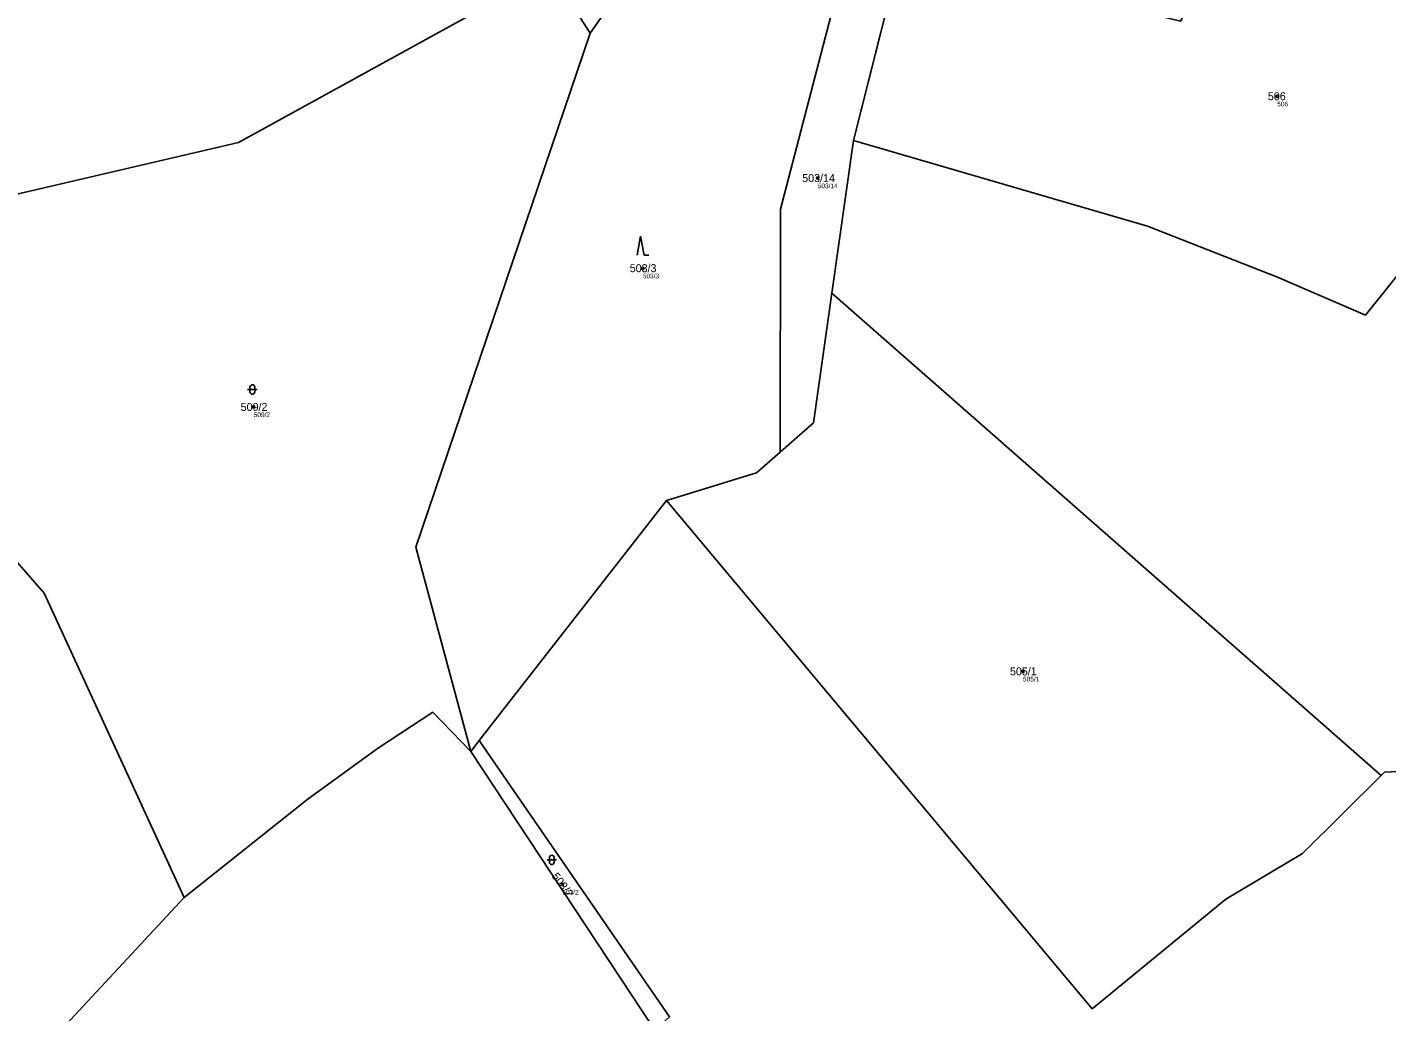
# Model space of a CAD drawing. Extents: x -766177 to -763254, y -1057727 to -1053915.
# Drawn here: x -765482.3 to -765193.5, y -1056306.7 to -1056097.6 of the extents above; entities that cross this region are included whole.
import ezdxf

# ---------------------------------------------------------------- set-up
doc = ezdxf.new("R2010")
doc.units = 0
for name, color, linetype in [('Vrstva 1', 7, 'Continuous'), ('Vrstva 2', 7, 'Continuous'), ('Vrstva 3', 7, 'Continuous'), ('Vrstva 50', 7, 'Continuous'), ('Vrstva 51', 7, 'Continuous')]:
    doc.layers.add(name, color=color, linetype=linetype)

msp = doc.modelspace()

# ---------------------------------------------------------------- linework, layer by layer
at = {"layer": 'Vrstva 1'}
for p, q in [((-765354.54, -1056087.11), (-765362.7, -1056098.87)), ((-765306.77, -1056121.63), (-765298.99, -1056090.69)), ((-765311.38, -1056154.08), (-765306.77, -1056121.63)), ((-765194.66, -1056256.52), (-765311.38, -1056154.08)), ((-765346.48, -1056198.15), (-765386.27, -1056249.12)), ((-765386.27, -1056249.12), (-765388.1, -1056251.45)), ((-765386.27, -1056249.12), (-765345.84, -1056307.83)), ((-765388.1, -1056251.45), (-765349, -1056310.65)), ((-765474.11, -1056309.49), (-765448.97, -1056282.49))]:
    msp.add_line(p, q, dxfattribs=at)
for points in [[(-765362.7, -1056098.87), (-765371.24, -1056085.63), (-765437.45, -1056122.1), (-765507.01, -1056138.29), (-765499.73, -1056153.48), (-765498.19, -1056169.01), (-765497.32, -1056190.86), (-765490.87, -1056203.92), (-765478.74, -1056217.81), (-765448.97, -1056282.49)], [(-765322.36, -1056187.86), (-765322.29, -1056136.23), (-765310.24, -1056089.97)], [(-765362.7, -1056098.87), (-765399.76, -1056208.05), (-765388.1, -1056251.45)], [(-765306.77, -1056121.63), (-765244.31, -1056139.87), (-765216.67, -1056150.71), (-765198.03, -1056158.78), (-765181.05, -1056137.66), (-765166.4, -1056113.67)], [(-765322.36, -1056187.86), (-765315.29, -1056181.63), (-765311.38, -1056154.08)], [(-765346.48, -1056198.15), (-765327.35, -1056192.26), (-765322.36, -1056187.86)], [(-765194.66, -1056256.52), (-765211.4, -1056273.13), (-765227.71, -1056282.83), (-765256.08, -1056306.1), (-765346.48, -1056198.15)], [(-765448.97, -1056282.49), (-765422.65, -1056261.47), (-765407.66, -1056250.64), (-765396.12, -1056243.1), (-765388.1, -1056251.45)], [(-765129.94, -1056253.12), (-765143.58, -1056253.3), (-765193.95, -1056255.81), (-765194.66, -1056256.52)]]:
    msp.add_lwpolyline(points, dxfattribs=at)
at = {"layer": 'Vrstva 3'}
for p, q in [((-765352, -1056141.98), (-765352.75, -1056145.98)), ((-765351.25, -1056145.98), (-765352, -1056141.98)), ((-765351.25, -1056145.98), (-765350.254, -1056145.98)), ((-765435.481, -1056174.541), (-765433.479, -1056174.541)), ((-765434.981, -1056174.041), (-765434.981, -1056175.042)), ((-765433.979, -1056175.042), (-765433.979, -1056174.041)), ((-765371.881, -1056274.481), (-765369.879, -1056274.481)), ((-765371.381, -1056273.981), (-765371.381, -1056274.982)), ((-765370.379, -1056274.982), (-765370.379, -1056273.981))]:
    msp.add_line(p, q, dxfattribs=at)
for centre, start, end in [((-765434.48, -1056174.0409), 0, 180), ((-765434.48, -1056175.0409), 180, 359.9878861), ((-765370.88, -1056273.9809), 0, 180), ((-765370.88, -1056274.9809), 180, 359.9878861)]:
    msp.add_arc(centre, 0.5, start, end, dxfattribs=at)
at = {"layer": 'Vrstva 50'}
for centre in [(-765216.77, -1056112.23994), (-765314.37, -1056129.62994), (-765351.54, -1056148.76994), (-765434.19, -1056178.24994), (-765270.76, -1056234.40994), (-765368.62, -1056279.68994)]:
    msp.add_circle(centre, 0.25, dxfattribs=at)
at = {"layer": 'Vrstva 51'}
for points in [[(-765507.01, -1056138.29), (-765437.45, -1056122.1), (-765371.24, -1056085.63), (-765362.7, -1056098.87), (-765354.54, -1056087.11), (-765353.46, -1056085.55), (-765369.17, -1056044.32), (-765393.26, -1056031.51), (-765387.38, -1056062.54), (-765593.55, -1056076.37)], [(-765143.58, -1056253.3), (-765193.95, -1056255.81), (-765194.66, -1056256.52), (-765211.4, -1056273.13), (-765227.71, -1056282.83), (-765256.08, -1056306.1), (-765346.48, -1056198.15), (-765386.27, -1056249.12), (-765345.84, -1056307.83)], [(-765474.11, -1056309.49), (-765448.97, -1056282.49), (-765478.74, -1056217.81), (-765490.87, -1056203.92)]]:
    msp.add_lwpolyline(points, dxfattribs=at)
for points in [[(-765223.4, -1056070.73), (-765237.3, -1056096.28), (-765296.76, -1056081.82), (-765298.99, -1056090.69), (-765306.77, -1056121.63), (-765244.31, -1056139.87), (-765216.67, -1056150.71), (-765198.03, -1056158.78), (-765181.05, -1056137.66), (-765166.4, -1056113.67), (-765143.12, -1056077.62), (-765218.53, -1056055.16)], [(-765499.73, -1056153.48), (-765498.19, -1056169.01), (-765497.32, -1056190.86), (-765490.87, -1056203.92), (-765478.74, -1056217.81), (-765448.97, -1056282.49), (-765422.65, -1056261.47), (-765407.66, -1056250.64), (-765396.12, -1056243.1), (-765388.1, -1056251.45), (-765399.76, -1056208.05), (-765362.7, -1056098.87), (-765371.24, -1056085.63), (-765437.45, -1056122.1), (-765507.01, -1056138.29)], [(-765327.35, -1056192.26), (-765322.36, -1056187.86), (-765322.29, -1056136.23), (-765310.24, -1056089.97), (-765346.41, -1056087.63), (-765354.54, -1056087.11), (-765362.7, -1056098.87), (-765399.76, -1056208.05), (-765388.1, -1056251.45), (-765386.27, -1056249.12), (-765346.48, -1056198.15)], [(-765311.38, -1056154.08), (-765306.77, -1056121.63), (-765298.99, -1056090.69), (-765306.29, -1056090.22), (-765310.24, -1056089.97), (-765322.29, -1056136.23), (-765322.36, -1056187.86), (-765315.29, -1056181.63)], [(-765092.46, -1056129.68), (-765166.4, -1056113.67), (-765181.05, -1056137.66), (-765198.03, -1056158.78), (-765216.67, -1056150.71), (-765244.31, -1056139.87), (-765306.77, -1056121.63), (-765311.38, -1056154.08), (-765194.66, -1056256.52), (-765193.95, -1056255.81), (-765143.58, -1056253.3), (-765129.94, -1056253.12), (-765101.53, -1056228.97), (-765091.79, -1056194.41), (-765081.16, -1056173.51), (-765076.46, -1056159.28), (-765086.71, -1056136.98)], [(-765194.66, -1056256.52), (-765311.38, -1056154.08), (-765315.29, -1056181.63), (-765322.36, -1056187.86), (-765327.35, -1056192.26), (-765346.48, -1056198.15), (-765256.08, -1056306.1), (-765227.71, -1056282.83), (-765211.4, -1056273.13)], [(-765435.92, -1056414.68), (-765423, -1056395.3), (-765411.65, -1056380.15), (-765373.52, -1056336.95), (-765349, -1056310.65), (-765388.1, -1056251.45), (-765396.12, -1056243.1), (-765407.66, -1056250.64), (-765422.65, -1056261.47), (-765448.97, -1056282.49), (-765474.11, -1056309.49), (-765468.33, -1056330.83), (-765477.15, -1056357.39), (-765460.21, -1056386.5), (-765438.68, -1056395.45), (-765445.32, -1056404.44)], [(-765388.1, -1056251.45), (-765349, -1056310.65), (-765345.84, -1056307.83), (-765386.27, -1056249.12)]]:
    msp.add_lwpolyline(points, close=True, dxfattribs=at)

# ---------------------------------------------------------------- texts
at = {"layer": 'Vrstva 2'}
for s, p in [('506', (-765218.744, -1056113.09)), ('503/14', (-765317.675, -1056130.48)), ('503/3', (-765354.313, -1056149.62)), ('509/2', (-765436.963, -1056179.1)), ('505/1', (-765273.533, -1056235.26))]:
    msp.add_text(s, height=1.699998, dxfattribs=at).set_placement(p)
msp.add_text('503/2', height=1.699998, rotation=307, dxfattribs=at).set_placement((-765370.967, -1056277.986))
at = {"layer": 'Vrstva 50'}
for s, p in [('506', (-765216.77, -1056114.396)), ('503/14', (-765314.37, -1056131.786)), ('503/3', (-765351.54, -1056150.926)), ('509/2', (-765434.19, -1056180.406)), ('505/1', (-765270.76, -1056236.566)), ('503/2', (-765368.62, -1056281.846))]:
    msp.add_text(s, height=0.999996, dxfattribs=at).set_placement(p)

doc.saveas('drawing.dxf')
